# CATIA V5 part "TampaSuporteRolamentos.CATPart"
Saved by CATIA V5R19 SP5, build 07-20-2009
Part number: TampaSuporteRolamentos
Bounding box of the stored display mesh (mm): x -17.5 to 17.5, y 0 to 2, z -17.5 to 17.5
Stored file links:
  Z:\UA\ATLAS\atlascar\ServoPiloto\dir\suportePotenciometro\V2\potenciometro\TampaSuporteRolamentos.CATPart
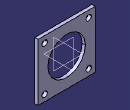
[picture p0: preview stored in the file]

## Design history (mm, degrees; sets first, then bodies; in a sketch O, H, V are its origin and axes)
Body1 (main body)
  Sketch1 on zx-plane, origin (0, 0, 0), H (-1, 0, 0), V (0, 0, 1)
    circle A1 centre (0, 0) radius 11.5
    line L1 (-17.5, 17.5) -> (17.5, 17.5)
    line L2 (17.5, 17.5) -> (17.5, -17.5)
    line L3 (17.5, -17.5) -> (-17.5, -17.5)
    line L4 (-17.5, -17.5) -> (-17.5, 17.5)
    circle A2 centre (13.5, 13.5) radius 1.75
    point P5 (13.5, 13.5)
    circle A3 centre (-13.5, 13.5) radius 1.75
    circle A4 centre (13.5, -13.5) radius 1.75
    circle A5 centre (-13.5, -13.5) radius 1.75
    radius A1 = 11.5
    distance L1 L3 = 35
    distance L2 L4 = 35
    distance L3 H = 17.5 {= Sketch1.distance(L1 L3) /2}
    distance V L2 = 17.5 {= Sketch1.distance(L2 L4) /2}
    radius A2 = 1.75
    distance P5 L2 = 4
    distance L1 P5 = 4
    horizontal: L1 H, L3 H
    vertical: L2 V, L4 V
    symmetry: A2 A3 V, A2 A4 H, A3 A5 H
  Pad1: profile Sketch1, direction (0, 1, 0), length 2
